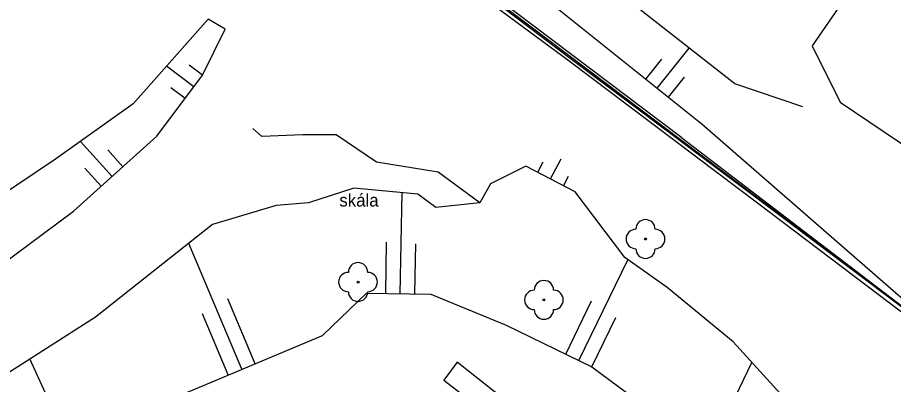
# Model space of a CAD drawing. Extents: x -639440 to -639026, y -1138850 to -1138262.
# Drawn here: x -639239.4 to -639194.21, y -1138621.6 to -1138602.66 of the extents above; entities that cross this region are included whole.
import ezdxf

# ---------------------------------------------------------------- set-up
doc = ezdxf.new("R2010")
doc.units = 0
for name, color, linetype in [('Vrstva 11', 7, 'Continuous'), ('Vrstva 14', 7, 'Continuous'), ('Vrstva 15', 7, 'Continuous'), ('Vrstva 22', 7, 'Continuous'), ('Vrstva 40', 7, 'Continuous'), ('Vrstva 7', 7, 'Continuous')]:
    doc.layers.add(name, color=color, linetype=linetype)

msp = doc.modelspace()

# ---------------------------------------------------------------- linework, layer by layer
at = {"layer": 'Vrstva 11'}
for p, q in [((-639196.13, -1138600.83), (-639198.4, -1138604.13)), ((-639205.13, -1138608.87), (-639214.65, -1138601.66)), ((-639198.4, -1138604.13), (-639196.95, -1138607.03)), ((-639196.95, -1138607.03), (-639189.58, -1138612.02)), ((-639222.05, -1138611.46), (-639224.38, -1138612.22)), ((-639218.74, -1138611.77), (-639222.05, -1138611.46)), ((-639217.82, -1138612.46), (-639218.74, -1138611.77)), ((-639224.38, -1138612.22), (-639226.05, -1138612.36)), ((-639215.55, -1138612.22), (-639217.82, -1138612.46))]:
    msp.add_line(p, q, dxfattribs=at)
at = {"layer": 'Vrstva 14'}
for p, q in [((-639202.39, -1138606.09), (-639213.7, -1138597.22)), ((-639214.05, -1138600.18), (-639204.07, -1138608.17)), ((-639229.57, -1138602.74), (-639233.43, -1138607.12)), ((-639228.69, -1138603.26), (-639229.57, -1138602.74)), ((-639229.85, -1138605.64), (-639228.69, -1138603.26)), ((-639232.21, -1138608.78), (-639229.85, -1138605.64)), ((-639198.89, -1138607.27), (-639202.39, -1138606.09)), ((-639233.43, -1138607.12), (-639237.43, -1138609.97)), ((-639204.07, -1138608.17), (-639190.04, -1138620.41)), ((-639226.8, -1138608.8), (-639227.26, -1138608.39)), ((-639224.68, -1138608.71), (-639226.8, -1138608.8)), ((-639222.96, -1138608.71), (-639224.68, -1138608.71)), ((-639220.88, -1138610.13), (-639222.96, -1138608.71)), ((-639236.51, -1138612.66), (-639232.21, -1138608.78)), ((-639205.13, -1138608.87), (-639190.04, -1138620.41)), ((-639237.43, -1138609.97), (-639241.05, -1138612.39)), ((-639217.69, -1138610.65), (-639220.88, -1138610.13)), ((-639213.17, -1138610.33), (-639215, -1138611.24)), ((-639210.63, -1138611.65), (-639213.17, -1138610.33)), ((-639215.55, -1138612.22), (-639217.69, -1138610.65)), ((-639215, -1138611.24), (-639215.55, -1138612.22)), ((-639208.07, -1138615.05), (-639210.63, -1138611.65)), ((-639226.05, -1138612.36), (-639229.33, -1138613.34)), ((-639240.28, -1138615.45), (-639236.51, -1138612.66)), ((-639229.33, -1138613.34), (-639235.37, -1138618.12)), ((-639205.89, -1138616.6), (-639208.07, -1138615.05)), ((-639223.66, -1138619.06), (-639221.4, -1138616.88)), ((-639221.4, -1138616.88), (-639218.07, -1138616.94)), ((-639202.48, -1138619.4), (-639205.89, -1138616.6)), ((-639218.07, -1138616.94), (-639214.18, -1138618.54)), ((-639235.37, -1138618.12), (-639242.69, -1138622.78)), ((-639214.18, -1138618.54), (-639209.76, -1138620.68)), ((-639231.73, -1138622.45), (-639223.66, -1138619.06)), ((-639198.81, -1138623.41), (-639202.48, -1138619.4)), ((-639216.71, -1138620.45), (-639217.41, -1138621.38)), ((-639214.31, -1138622.36), (-639216.71, -1138620.45)), ((-639209.76, -1138620.68), (-639206.89, -1138622.81)), ((-639217.41, -1138621.38), (-639212.56, -1138625.05))]:
    msp.add_line(p, q, dxfattribs=at)
at = {"layer": 'Vrstva 15'}
for p, q in [((-639206.399, -1138606.305), (-639204.747, -1138604.242)), ((-639229.85, -1138605.64), (-639230.534, -1138605.126)), ((-639206.985, -1138605.837), (-639206.161, -1138604.808)), ((-639230.3, -1138606.239), (-639231.716, -1138605.175)), ((-639205.814, -1138606.774), (-639204.985, -1138605.739)), ((-639230.751, -1138606.839), (-639231.482, -1138606.289)), ((-639234.517, -1138610.862), (-639236.147, -1138609.056)), ((-639233.96, -1138610.359), (-639234.746, -1138609.488)), ((-639212.558, -1138610.648), (-639212.278, -1138610.11)), ((-639211.893, -1138610.994), (-639211.354, -1138609.956)), ((-639235.074, -1138611.364), (-639235.918, -1138610.429)), ((-639211.227, -1138611.34), (-639210.968, -1138610.841)), ((-639219.651, -1138616.912), (-639219.557, -1138611.693)), ((-639227.831, -1138620.812), (-639230.561, -1138614.314)), ((-639220.401, -1138616.898), (-639220.354, -1138614.261)), ((-639218.901, -1138616.925), (-639218.855, -1138614.344)), ((-639210.435, -1138620.353), (-639207.919, -1138615.157)), ((-639227.14, -1138620.522), (-639228.545, -1138617.176)), ((-639211.11, -1138620.026), (-639209.782, -1138617.283)), ((-639228.523, -1138621.103), (-639229.847, -1138617.95)), ((-639209.76, -1138620.68), (-639208.53, -1138618.139)), ((-639236.709, -1138624.741), (-639238.762, -1138620.28)), ((-639203.387, -1138624.377), (-639201.513, -1138620.457))]:
    msp.add_line(p, q, dxfattribs=at)
at = {"layer": 'Vrstva 22'}
for centre in [(-639207, -1138614.09), (-639221.83, -1138616.31), (-639212.24, -1138617.23)]:
    msp.add_circle(centre, 0.05, dxfattribs=at)
for centre, start, end in [((-639207, -1138613.59), 0, 180), ((-639207.5, -1138614.09), 90, 270), ((-639206.5, -1138614.09), 270, 90), ((-639207, -1138614.59), 180, 0), ((-639221.83, -1138615.81), 0, 180), ((-639222.33, -1138616.31), 90, 270), ((-639221.33, -1138616.31), 270, 90), ((-639212.24, -1138616.73), 0, 180), ((-639221.83, -1138616.81), 180, 0), ((-639212.74, -1138617.23), 90, 270), ((-639211.74, -1138617.23), 270, 90), ((-639212.24, -1138617.73), 180, 0)]:
    msp.add_arc(centre, 0.5, start, end, dxfattribs=at)
at = {"layer": 'Vrstva 7'}
for p, q in [((-639210.94, -1138604.92), (-639216.37, -1138600.89)), ((-639190.04, -1138620.41), (-639216.21, -1138600.66)), ((-639210.95, -1138604.73), (-639216.2, -1138600.75)), ((-639200.96, -1138612.21), (-639210.95, -1138604.73)), ((-639201.16, -1138612.3), (-639210.94, -1138604.92)), ((-639190.26, -1138620.55), (-639201.16, -1138612.3)), ((-639190.04, -1138620.41), (-639200.96, -1138612.21))]:
    msp.add_line(p, q, dxfattribs=at)

# ---------------------------------------------------------------- texts
at = {"layer": 'Vrstva 40'}
msp.add_text('skála', height=0.65, dxfattribs=at).set_placement((-639222.796, -1138612.415))

doc.saveas('drawing.dxf')
